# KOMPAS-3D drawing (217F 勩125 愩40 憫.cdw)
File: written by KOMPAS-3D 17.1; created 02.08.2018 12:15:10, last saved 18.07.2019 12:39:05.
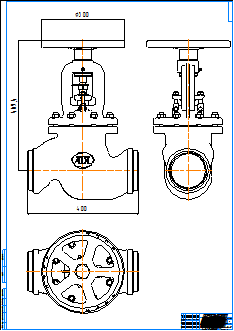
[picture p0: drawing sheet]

Sheet 1: A0, portrait

Title block, sheet 1: name: 217F Ду125 Ру40 СС; material: Внимание! Данный продукт является объектом авторского права ООО «Торговый Дом АДЛ». / Запрещается изменение, копирование, распространение / (в том числе путем копирования на другие сайты и ресурсы в Интернете) / или любое иное использование информации и объектов без предварительного / согласия правообладателя (ООО «Торговый Дом АДЛ»).; sheets: 1; organisation: ООО "Торговый дом АДЛ"; sheet format: A0; stored path: \\adlc.lan\data\АДЛ_ПКД\3D-модели\Поставщики\Zetkama\Вентили\217F\KOMPAS 2D\217F Ду125 Ру40 СС.cdw

Views: Проекционный вид 3
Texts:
  kka
  adl
Dimensions and other numbers on the sheet: 1:1; 1; 217F Ду125 Ру40 СС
